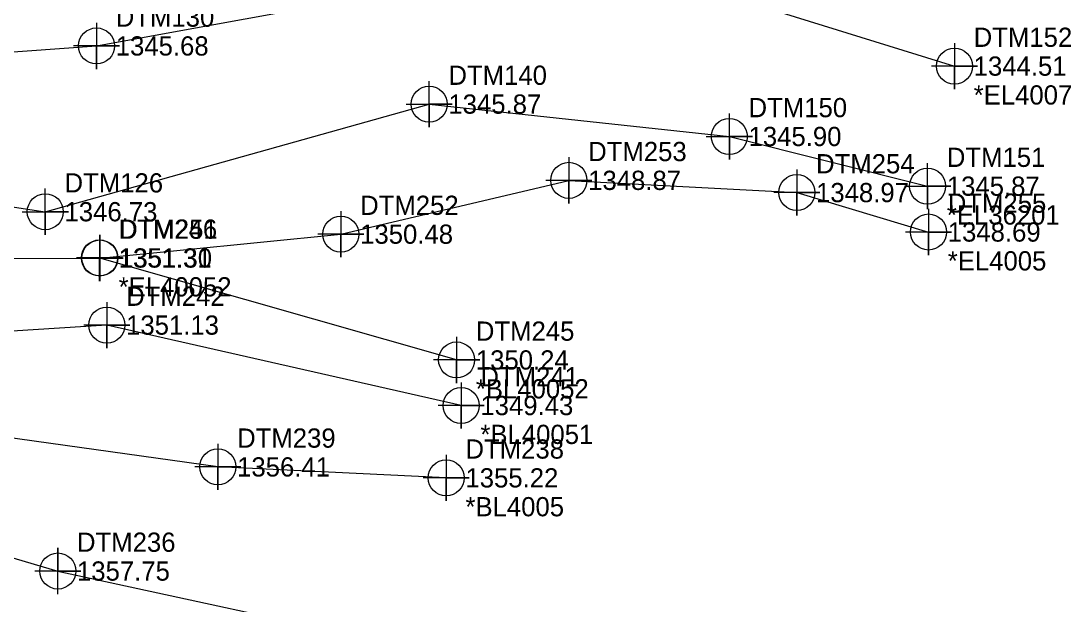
# Model space of a CAD drawing. Extents: x 1251905 to 1252853, y 859795 to 860170.
# Drawn here: x 1252087.6 to 1252224.2, y 859945.7 to 860021.6 of the extents above; entities that cross this region are included whole.
import ezdxf

# ---------------------------------------------------------------- set-up
doc = ezdxf.new("R2010")
doc.units = 0
for name, color, linetype in [('Exist DTM Breakline', 7, 'Continuous'), ('Exist DTM Breakline Cogo Comment', 7, 'Continuous'), ('Exist DTM Breakline Cogo Elevation', 7, 'Continuous'), ('Exist DTM Breakline Cogo Number', 7, 'Continuous'), ('Exist DTM Breakline Cogo Point CELL', 7, 'Continuous'), ('Exist DTM Breakline Underwater', 7, 'Continuous'), ('Exist DTM Breakline Underwater Cogo Comment', 7, 'Continuous'), ('Exist DTM Breakline Underwater Cogo Elevation', 7, 'Continuous'), ('Exist DTM Breakline Underwater Cogo Number', 7, 'Continuous'), ('Exist DTM Breakline Underwater Cogo Point CELL', 7, 'Continuous'), ('Exist Hydro Stream or Body of Water', 7, 'Continuous'), ('Exist Hydro Stream or Body of Water Cogo Comment', 7, 'Continuous'), ('Exist Hydro Stream or Body of Water Cogo Elevation', 7, 'Continuous'), ('Exist Hydro Stream or Body of Water Cogo Number', 7, 'Continuous'), ('Exist Hydro Stream or Body of Water Cogo Point CELL', 7, 'Continuous'), ('Exist Roads Soil', 7, 'Continuous'), ('Exist Roads Soil Cogo Elevation', 7, 'Continuous'), ('Exist Roads Soil Cogo Number', 7, 'Continuous'), ('Exist Roads Soil Cogo Point CELL', 7, 'Continuous')]:
    doc.layers.add(name, color=color, linetype=linetype)

msp = doc.modelspace()

# ---------------------------------------------------------------- linework, layer by layer
at = {"layer": 'Exist DTM Breakline'}
msp.add_line((1252144.286, 859977.52), (1252098.18, 859990.679), dxfattribs=at)
for points in [[(1252142.933, 859962.19), (1252113.232, 859963.613), (1252069.451, 859969.754), (1252053.554, 859975.248), (1252049.013, 859995.838), (1252055.18, 859990.86), (1252070.476, 859990.723), (1252097.889, 859990.776), (1252129.235, 859993.878), (1252158.893, 860000.874), (1252188.538, 859999.284), (1252205.671, 859994.157)], [(1252144.878, 859971.595), (1252098.791, 859982.055), (1252067.947, 859980.078), (1252056.401, 859988.682)]]:
    msp.add_lwpolyline(points, dxfattribs=at)
at = {"layer": 'Exist DTM Breakline Cogo Point CELL'}
for points in [[(1252158.893, 860003.874), (1252158.893, 859997.874), (1252158.893, 860000.874), (1252161.893, 860000.874), (1252155.893, 860000.874)], [(1252188.538, 860002.284), (1252188.538, 859996.284), (1252188.538, 859999.284), (1252191.538, 859999.284), (1252185.538, 859999.284)], [(1252129.235, 859996.878), (1252129.235, 859990.878), (1252129.235, 859993.878), (1252132.235, 859993.878), (1252126.235, 859993.878)], [(1252205.671, 859997.157), (1252205.671, 859991.157), (1252205.671, 859994.157), (1252208.671, 859994.157), (1252202.671, 859994.157)], [(1252097.82, 859993.782), (1252097.82, 859987.782), (1252097.82, 859990.782), (1252100.82, 859990.782), (1252094.82, 859990.782)], [(1252097.889, 859993.776), (1252097.889, 859987.776), (1252097.889, 859990.776), (1252100.889, 859990.776), (1252094.889, 859990.776)], [(1252098.791, 859985.055), (1252098.791, 859979.055), (1252098.791, 859982.055), (1252101.791, 859982.055), (1252095.791, 859982.055)], [(1252144.286, 859980.52), (1252144.286, 859974.52), (1252144.286, 859977.52), (1252147.286, 859977.52), (1252141.286, 859977.52)], [(1252144.878, 859974.595), (1252144.878, 859968.595), (1252144.878, 859971.595), (1252147.878, 859971.595), (1252141.878, 859971.595)], [(1252113.232, 859966.613), (1252113.232, 859960.613), (1252113.232, 859963.613), (1252116.232, 859963.613), (1252110.232, 859963.613)], [(1252142.933, 859965.19), (1252142.933, 859959.19), (1252142.933, 859962.19), (1252145.933, 859962.19), (1252139.933, 859962.19)]]:
    msp.add_lwpolyline(points, dxfattribs=at)
for centre in [(1252158.893, 860000.874), (1252188.538, 859999.284), (1252129.235, 859993.878), (1252205.671, 859994.157), (1252097.82, 859990.782), (1252097.889, 859990.776), (1252098.791, 859982.055), (1252144.286, 859977.52), (1252144.878, 859971.595), (1252113.232, 859963.613), (1252142.933, 859962.19)]:
    msp.add_circle(centre, 2.344, dxfattribs=at)
at = {"layer": 'Exist DTM Breakline Underwater'}
msp.add_lwpolyline([(1251927.42, 860049.663), (1251960.607, 860043.428), (1251991.544, 860038.543), (1252023.095, 860021.002), (1252051.108, 860015.006), (1252097.444, 860018.35), (1252136.124, 860025.415), (1252179.795, 860024.836), (1252209.042, 860015.729)], dxfattribs=at)
at = {"layer": 'Exist DTM Breakline Underwater Cogo Point CELL'}
for points in [[(1252097.444, 860021.35), (1252097.444, 860015.35), (1252097.444, 860018.35), (1252100.444, 860018.35), (1252094.444, 860018.35)], [(1252209.042, 860018.729), (1252209.042, 860012.729), (1252209.042, 860015.729), (1252212.042, 860015.729), (1252206.042, 860015.729)]]:
    msp.add_lwpolyline(points, dxfattribs=at)
for centre in [(1252097.444, 860018.35), (1252209.042, 860015.729)]:
    msp.add_circle(centre, 2.344, dxfattribs=at)
at = {"layer": 'Exist Hydro Stream or Body of Water'}
msp.add_lwpolyline([(1251923.519, 860032.492), (1251957.999, 860032.964), (1251987.699, 860026.743), (1252004.412, 860018.883), (1252004.612, 860014.582), (1251994.716, 860013.049), (1252010.915, 860007.676), (1252019.462, 860003.97), (1252019.665, 860004.195), (1252046.38, 860003.539), (1252090.782, 859996.797), (1252140.715, 860010.791), (1252179.759, 860006.581), (1252205.549, 860000.12)], dxfattribs=at)
at = {"layer": 'Exist Hydro Stream or Body of Water Cogo Point CELL'}
for points in [[(1252137.715, 860010.791), (1252143.715, 860010.791), (1252140.715, 860010.791), (1252140.715, 860007.791), (1252140.715, 860013.791)], [(1252176.759, 860006.581), (1252182.759, 860006.581), (1252179.759, 860006.581), (1252179.759, 860003.581), (1252179.759, 860009.581)], [(1252202.549, 860000.12), (1252208.549, 860000.12), (1252205.549, 860000.12), (1252205.549, 859997.12), (1252205.549, 860003.12)], [(1252087.782, 859996.797), (1252093.782, 859996.797), (1252090.782, 859996.797), (1252090.782, 859993.797), (1252090.782, 859999.797)]]:
    msp.add_lwpolyline(points, dxfattribs=at)
for centre in [(1252140.715, 860010.791), (1252179.759, 860006.581), (1252205.549, 860000.12), (1252090.782, 859996.797)]:
    msp.add_circle(centre, 2.344, dxfattribs=at)
at = {"layer": 'Exist Roads Soil'}
msp.add_lwpolyline([(1252044.791, 859969.904), (1252064.824, 859958.222), (1252092.402, 859950.074), (1252137.619, 859940.278)], dxfattribs=at)
at = {"layer": 'Exist Roads Soil Cogo Point CELL'}
msp.add_lwpolyline([(1252092.402, 859947.074), (1252092.402, 859953.074), (1252092.402, 859950.074), (1252095.402, 859950.074), (1252089.402, 859950.074)], dxfattribs=at)
msp.add_circle((1252092.402, 859950.074), 2.344, dxfattribs=at)

# ---------------------------------------------------------------- texts
at = {"layer": 'Exist DTM Breakline Cogo Comment'}
for s, p in [('*EL4005', (1252208.171, 859989.157)), ('*EL40052', (1252100.32, 859985.782)), ('*BL40052', (1252146.786, 859972.52)), ('*BL40051', (1252147.378, 859966.595)), ('*BL4005', (1252145.433, 859957.19))]:
    msp.add_text(s, height=2.5, dxfattribs=at).set_placement(p)
at = {"layer": 'Exist DTM Breakline Cogo Elevation'}
for s, p in [('1348.87', (1252161.393, 859999.624)), ('1348.97', (1252191.038, 859998.034)), ('1350.48', (1252131.735, 859992.628)), ('1348.69', (1252208.171, 859992.907)), ('1351.31', (1252100.32, 859989.532)), ('1351.30', (1252100.389, 859989.526)), ('1351.13', (1252101.291, 859980.805)), ('1350.24', (1252146.786, 859976.27)), ('1349.43', (1252147.378, 859970.345)), ('1356.41', (1252115.732, 859962.363)), ('1355.22', (1252145.433, 859960.94))]:
    msp.add_text(s, height=2.5, dxfattribs=at).set_placement(p)
at = {"layer": 'Exist DTM Breakline Cogo Number'}
for s, p in [('DTM253', (1252161.393, 860003.374)), ('DTM254', (1252191.038, 860001.784)), ('DTM255', (1252208.171, 859996.657)), ('DTM252', (1252131.735, 859996.378)), ('DTM246', (1252100.32, 859993.282)), ('DTM251', (1252100.389, 859993.276)), ('DTM242', (1252101.291, 859984.555)), ('DTM245', (1252146.786, 859980.02)), ('DTM241', (1252147.378, 859974.095)), ('DTM239', (1252115.732, 859966.113)), ('DTM238', (1252145.433, 859964.69))]:
    msp.add_text(s, height=2.5, dxfattribs=at).set_placement(p)
at = {"layer": 'Exist DTM Breakline Underwater Cogo Comment'}
msp.add_text('*EL4007', height=2.5, dxfattribs=at).set_placement((1252211.542, 860010.729))
at = {"layer": 'Exist DTM Breakline Underwater Cogo Elevation'}
for s, p in [('1345.68', (1252099.944, 860017.1)), ('1344.51', (1252211.542, 860014.479))]:
    msp.add_text(s, height=2.5, dxfattribs=at).set_placement(p)
at = {"layer": 'Exist DTM Breakline Underwater Cogo Number'}
for s, p in [('DTM130', (1252099.944, 860020.85)), ('DTM152', (1252211.542, 860018.229))]:
    msp.add_text(s, height=2.5, dxfattribs=at).set_placement(p)
at = {"layer": 'Exist Hydro Stream or Body of Water Cogo Comment'}
msp.add_text('*EL36201', height=2.5, dxfattribs=at).set_placement((1252208.049, 859995.12))
at = {"layer": 'Exist Hydro Stream or Body of Water Cogo Elevation'}
for s, p in [('1345.87', (1252143.215, 860009.541)), ('1345.90', (1252182.259, 860005.331)), ('1345.87', (1252208.049, 859998.87)), ('1346.73', (1252093.282, 859995.547))]:
    msp.add_text(s, height=2.5, dxfattribs=at).set_placement(p)
at = {"layer": 'Exist Hydro Stream or Body of Water Cogo Number'}
for s, p in [('DTM140', (1252143.215, 860013.291)), ('DTM150', (1252182.259, 860009.081)), ('DTM151', (1252208.049, 860002.62)), ('DTM126', (1252093.282, 859999.297))]:
    msp.add_text(s, height=2.5, dxfattribs=at).set_placement(p)
at = {"layer": 'Exist Roads Soil Cogo Elevation'}
msp.add_text('1357.75', height=2.5, dxfattribs=at).set_placement((1252094.902, 859948.824))
at = {"layer": 'Exist Roads Soil Cogo Number'}
msp.add_text('DTM236', height=2.5, dxfattribs=at).set_placement((1252094.902, 859952.574))

doc.saveas('drawing.dxf')
